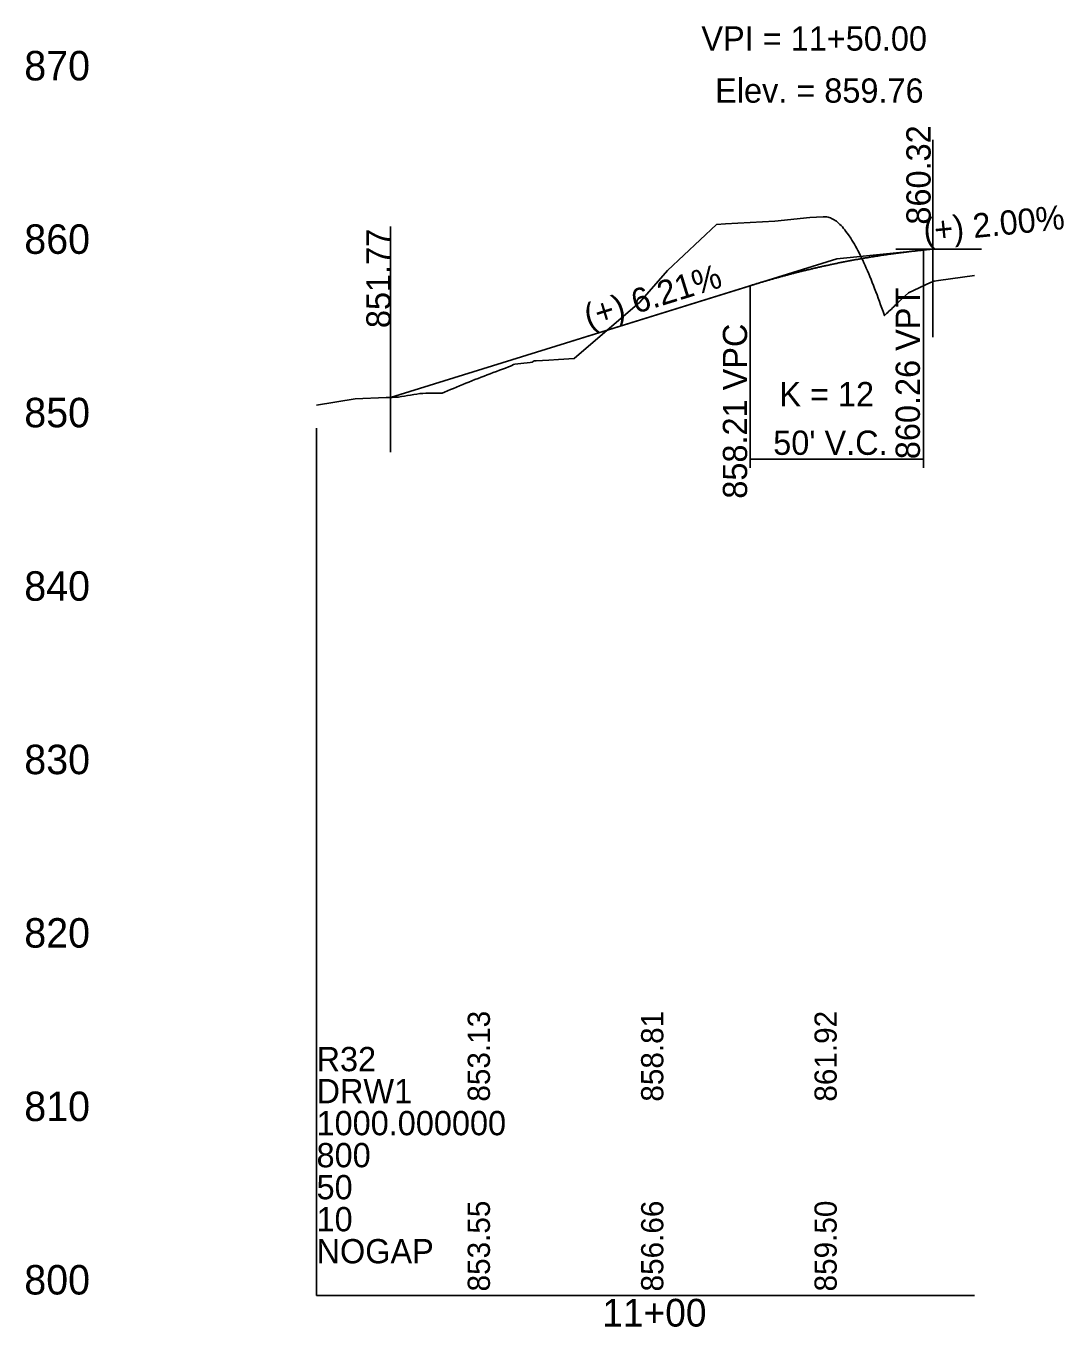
# Model space of a CAD drawing. Extents: x 1459978 to 1464152, y 1125650 to 1128602.
# Drawn here: x 1459978.4 to 1460277.7, y 1125650 to 1126025.1 of the extents above; entities that cross this region are included whole.
import ezdxf

# ---------------------------------------------------------------- set-up
doc = ezdxf.new("R2010")
doc.units = 0
for name, color, linetype in [('BR_USER NOTES', 7, 'Continuous'), ('RD_DDB_ElevTX', 7, 'Continuous'), ('RD_DDB_GradeTX', 7, 'Continuous'), ('RD_DDB_Profile_EX', 7, 'Continuous'), ('RD_DDB_Profile_Lbl', 7, 'Continuous'), ('RD_DDB_Profile_PR', 7, 'Continuous'), ('RD_DDB_StaTX', 7, 'Continuous'), ('RD_DDB_StripGrade', 7, 'Continuous'), ('RD_DDB_VCLbl', 7, 'Continuous'), ('RD_GPK_Profile_Cell', 7, 'Continuous')]:
    doc.layers.add(name, color=color, linetype=linetype)

msp = doc.modelspace()

# ---------------------------------------------------------------- linework, layer by layer
at = {"layer": 'BR_USER NOTES'}
for p, q in [((1460239.93, 1125992.21), (1460239.93, 1125935.4)), ((1460083.53, 1125967.26), (1460083.53, 1125902.23)), ((1460229.21, 1125960.72), (1460253.97, 1125960.72))]:
    msp.add_line(p, q, dxfattribs=at)
at = {"layer": 'RD_DDB_GradeTX'}
for p in [(1460135.78, 1125934.21), (1460239.93, 1125960.72)]:
    msp.add_line(p, (1460212.18, 1125957.95), dxfattribs=at)
at = {"layer": 'RD_DDB_Profile_EX'}
msp.add_lwpolyline([(1460062.18, 1125915.76), (1460073.34, 1125917.56), (1460082.26, 1125917.92), (1460083.14, 1125917.96), (1460084.02, 1125917.99), (1460084.91, 1125918.03), (1460085.49, 1125918.05), (1460085.79, 1125918.1), (1460086.67, 1125918.24), (1460087.56, 1125918.38), (1460088.44, 1125918.52), (1460089.32, 1125918.66), (1460090.21, 1125918.8), (1460091.09, 1125918.93), (1460091.97, 1125919.07), (1460092.5, 1125919.15), (1460092.85, 1125919.15), (1460093.74, 1125919.17), (1460094.62, 1125919.18), (1460095.5, 1125919.19), (1460096.39, 1125919.2), (1460097.27, 1125919.2), (1460098.36, 1125919.21), (1460099.04, 1125919.49), (1460099.92, 1125919.87), (1460100.8, 1125920.24), (1460101.68, 1125920.6), (1460102.57, 1125920.97), (1460103.45, 1125921.33), (1460104.33, 1125921.69), (1460105.22, 1125922.05), (1460106.1, 1125922.41), (1460106.98, 1125922.76), (1460107.87, 1125923.11), (1460108.75, 1125923.46), (1460109.63, 1125923.8), (1460110.51, 1125924.14), (1460111.4, 1125924.48), (1460112.28, 1125924.82), (1460113.16, 1125925.16), (1460114.05, 1125925.49), (1460114.93, 1125925.82), (1460115.81, 1125926.14), (1460116.7, 1125926.46), (1460117.58, 1125926.79), (1460118.16, 1125926.99), (1460118.46, 1125927.18), (1460118.99, 1125927.5), (1460119.34, 1125927.55), (1460120.23, 1125927.67), (1460121.11, 1125927.79), (1460121.99, 1125927.9), (1460122.88, 1125928), (1460123.76, 1125928.1), (1460124.34, 1125928.17), (1460124.64, 1125928.32), (1460124.97, 1125928.49), (1460125.53, 1125928.53), (1460129.14, 1125928.76), (1460131.93, 1125928.94), (1460136.44, 1125929.23), (1460155.45, 1125945.4), (1460163.41, 1125954.59), (1460177.54, 1125967.88), (1460180.09, 1125968.03), (1460194.3, 1125968.83), (1460204.48, 1125969.87), (1460208.31, 1125970.09), (1460208.65, 1125970.09), (1460209, 1125970.08), (1460209.34, 1125970.03), (1460209.69, 1125969.96), (1460210.03, 1125969.86), (1460210.38, 1125969.74), (1460210.72, 1125969.59), (1460211.07, 1125969.42), (1460211.41, 1125969.22), (1460211.76, 1125968.99), (1460212.1, 1125968.75), (1460212.45, 1125968.47), (1460212.79, 1125968.17), (1460213.13, 1125967.85), (1460213.48, 1125967.5), (1460213.82, 1125967.12), (1460214.17, 1125966.72), (1460214.51, 1125966.3), (1460214.86, 1125965.85), (1460215.2, 1125965.38), (1460215.55, 1125964.89), (1460216.24, 1125963.85), (1460216.58, 1125963.32), (1460216.93, 1125962.76), (1460217.27, 1125962.18), (1460217.61, 1125961.58), (1460217.96, 1125960.95), (1460218.3, 1125960.31), (1460218.65, 1125959.65), (1460218.99, 1125958.97), (1460219.34, 1125958.26), (1460219.68, 1125957.54), (1460220.03, 1125956.8), (1460220.37, 1125956.04), (1460220.72, 1125955.26), (1460221.06, 1125954.47), (1460221.41, 1125953.65), (1460221.75, 1125952.82), (1460222.09, 1125951.98), (1460222.44, 1125951.12), (1460222.78, 1125950.24), (1460223.13, 1125949.34), (1460223.47, 1125948.44), (1460223.82, 1125947.52), (1460224.16, 1125946.58), (1460224.51, 1125945.63), (1460224.85, 1125944.67), (1460225.2, 1125943.7), (1460225.54, 1125942.71), (1460225.94, 1125941.57), (1460226.57, 1125942.16), (1460226.92, 1125942.48), (1460227.26, 1125942.81), (1460227.61, 1125943.14), (1460227.95, 1125943.46), (1460228.3, 1125943.8), (1460228.64, 1125944.13), (1460228.99, 1125944.46), (1460229.33, 1125944.8), (1460229.68, 1125945.13), (1460230.02, 1125945.47), (1460230.37, 1125945.81), (1460230.71, 1125946.15), (1460231.09, 1125946.52), (1460232.89, 1125948.16), (1460239.27, 1125951.1), (1460240.25, 1125951.52), (1460241.58, 1125951.72), (1460251.93, 1125953.12)], dxfattribs=at)
at = {"layer": 'RD_DDB_Profile_PR'}
for p, q in [((1460237.18, 1125960.45), (1460239.93, 1125960.72)), ((1460083.53, 1125917.97), (1460187.18, 1125950.18))]:
    msp.add_line(p, q, dxfattribs=at)
msp.add_spline([(1460187.18, 1125950.18), (1460188.18, 1125950.49), (1460189.18, 1125950.79), (1460190.18, 1125951.09), (1460191.18, 1125951.39), (1460192.18, 1125951.68), (1460193.18, 1125951.97), (1460194.18, 1125952.25), (1460195.18, 1125952.53), (1460196.18, 1125952.81), (1460197.18, 1125953.08), (1460198.18, 1125953.34), (1460199.18, 1125953.61), (1460200.18, 1125953.86), (1460201.18, 1125954.12), (1460202.18, 1125954.37), (1460203.18, 1125954.61), (1460204.18, 1125954.85), (1460205.18, 1125955.09), (1460206.18, 1125955.32), (1460207.18, 1125955.55), (1460208.18, 1125955.78), (1460209.18, 1125956), (1460210.18, 1125956.21), (1460211.18, 1125956.42), (1460212.18, 1125956.63), (1460213.18, 1125956.84), (1460214.18, 1125957.03), (1460215.18, 1125957.23), (1460216.18, 1125957.42), (1460217.18, 1125957.61), (1460218.18, 1125957.79), (1460219.18, 1125957.97), (1460220.18, 1125958.14), (1460221.18, 1125958.31), (1460222.18, 1125958.48), (1460223.18, 1125958.64), (1460224.18, 1125958.79), (1460225.18, 1125958.95), (1460226.18, 1125959.09), (1460227.18, 1125959.24), (1460228.18, 1125959.38), (1460229.18, 1125959.51), (1460230.18, 1125959.65), (1460231.18, 1125959.77), (1460232.18, 1125959.9), (1460233.18, 1125960.02), (1460234.18, 1125960.13), (1460235.18, 1125960.24), (1460236.18, 1125960.35), (1460237.18, 1125960.45)], degree=3, dxfattribs=at)
at = {"layer": 'RD_DDB_VCLbl'}
for p, q in [((1460237.18, 1125897.68), (1460237.18, 1125960.45)), ((1460187.18, 1125897.68), (1460187.18, 1125950.18)), ((1460187.18, 1125900.18), (1460237.18, 1125900.18))]:
    msp.add_line(p, q, dxfattribs=at)
at = {"layer": 'RD_GPK_Profile_Cell'}
for q in [(1460062.18, 1125909.12), (1460251.93, 1125659.12), (1460062.18, 1125659.12)]:
    msp.add_line((1460062.18, 1125659.12), q, dxfattribs=at)

# ---------------------------------------------------------------- texts
at = {"layer": 'RD_DDB_ElevTX'}
for s, p in [('870', (1459977.9, 1126009.37)), ('860', (1459977.9, 1125959.37)), ('850', (1459977.9, 1125909.37)), ('840', (1459977.9, 1125859.37)), ('830', (1459977.9, 1125809.37)), ('820', (1459977.9, 1125759.37)), ('810', (1459977.9, 1125709.37)), ('800', (1459977.9, 1125659.37))]:
    msp.add_text(s, height=8.5, dxfattribs=at).set_placement(p)
at = {"layer": 'RD_DDB_GradeTX'}
for s, rotation, p in [('(+) 2.00%', 5.7106, (1460237.53, 1125962.49)), ('(+) 6.21%', 17.262, (1460140.61, 1125937.8))]:
    msp.add_text(s, height=7, rotation=rotation, dxfattribs=at).set_placement(p)
at = {"layer": 'RD_DDB_Profile_Lbl'}
for s, p in [('VPI = 11+50.00', (1460173.16, 1126017.95)), ('Elev. = 859.76', (1460177.13, 1126002.95))]:
    msp.add_text(s, height=7, dxfattribs=at).set_placement(p)
for s, p in [('860.32', (1460239.27, 1125967.8)), ('851.77', (1460083.53, 1125937.97))]:
    msp.add_text(s, height=7, rotation=90, dxfattribs=at).set_placement(p)
at = {"layer": 'RD_DDB_StaTX'}
msp.add_text('11+00', height=8, dxfattribs=at).set_placement((1460144.59, 1125650.12))
at = {"layer": 'RD_DDB_StripGrade'}
for s, height, p in [('860.26 VPT', 7, (1460236.18, 1125900.18)), ('858.21 VPC', 7, (1460186.35, 1125888.79)), ('853.13', 6.4, (1460112.18, 1125714.97)), ('858.81', 6.4, (1460162.18, 1125714.97)), ('861.92', 6.4, (1460212.18, 1125714.97)), ('853.55', 6.4, (1460112.18, 1125660.26)), ('856.66', 6.4, (1460162.18, 1125660.26)), ('859.50', 6.4, (1460212.18, 1125660.26))]:
    msp.add_text(s, height=height, rotation=90, dxfattribs=at).set_placement(p)
at = {"layer": 'RD_DDB_VCLbl'}
for s, p in [('K = 12', (1460195.64, 1125915.43)), ("50' V.C.", (1460193.87, 1125901.43))]:
    msp.add_text(s, height=7, dxfattribs=at).set_placement(p)
at = {"layer": 'RD_GPK_Profile_Cell'}
for s, p in [('R32', (1460062.18, 1125723.74)), ('DRW1', (1460062.18, 1125714.51)), ('1000.000000', (1460062.18, 1125705.28)), ('800', (1460062.18, 1125696.05)), ('50', (1460062.18, 1125686.82)), ('10', (1460062.18, 1125677.59)), ('NOGAP', (1460062.18, 1125668.36))]:
    msp.add_text(s, height=7, dxfattribs=at).set_placement(p)

doc.saveas('drawing.dxf')
